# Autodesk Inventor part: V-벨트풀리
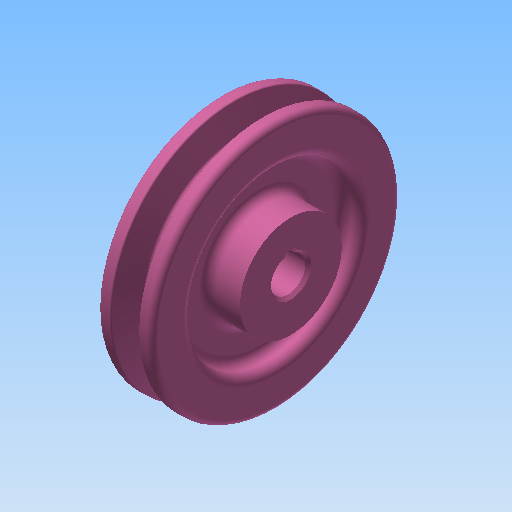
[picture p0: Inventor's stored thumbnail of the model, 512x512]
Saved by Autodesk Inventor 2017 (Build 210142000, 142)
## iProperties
Created: 2020-07
Part Number: V-벨트풀리
Material: 알루미늄 6061
Document SubType Name: Modeling
Designer: mduedu
Density: 2.71 g/cm^3
Mass: 204.704 g
Surface Area: 223.016 cm^2
Volume: 75.5367 cm^3
Appearance: 분홍색
Author: mduedu
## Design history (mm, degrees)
sketch "스케치1"
  geometry: L1 (-9.5, 0)-(9.5, 0); L2 (9.5, 0)-(9.5, 42.7); L3 (9.5, 42.7)-(-9.5, 42.7); L4 (-9.5, 42.7)-(-9.5, 0); L5 (0, 0)-(0, 42.7); L6 (-4.877, 42.7)-(-1.953, 33.7); L7 (-1.953, 33.7)-(1.953, 33.7); L8 (1.953, 33.7)-(4.877, 42.7); L9 (-9.5, 40)-(9.5, 40); 3 further points
  constraints: 18 end point, 8 point on line, 3 perpendicular, 2 midpoint, 2 parallel, 1 coincident, 1 horizontal, 1 other
  dimensions: "d0" = 85.4 diameter of L3 L1; "d2" = 8 distance of point (4, 40) point (-4, 40); "d3" = 2.7 distance between parallel lines of L9 L3; "d4" = 6.3 distance between parallel lines of L7 L9; "d5" = 36 deg angle of L8 L6; "d6" = 19 distance between parallel lines of L2 L4
revolve "회전1" sketch "스케치1" stored, may be unused: angle "d7" = 90 deg
fillet "모깎기1" dims "d8" = 0.5, "d9" = 1, "d10" = 2
sketch "스케치2"
  geometry: C1 r 17.5 at (0, 0); C2 r 29 at (0, 0); 1 further point
  constraints: 2 centre point, 2 coincident
  dimensions: "d11" = 35 diameter of C1; "d12" = 58 diameter of C2
extrude "돌출1" cut sketch "스케치2" distance "d13" = 6; taper "d14" = 0 deg
fillet "모깎기2" dims "d15" = 3
sketch "스케치3"
  geometry: C1 r 17.5 at (0, 0) reference; 1 further point
extrude "돌출2" join sketch "스케치3" distance "d16" = 5; taper "d17" = 0 deg
sketch "스케치4"
  geometry: L1 (-2, 5.657)-(2, 5.657); L2 (2, 5.657)-(2, 7.8); L3 (2, 7.8)-(-2, 7.8); L4 (-2, 7.8)-(-2, 5.657); A1 r 6 centre (0, 0) between (-2, 5.657) and (2, 5.657); 1 further point
  constraints: 8 end point, 2 parallel, 2 point on circle, 1 centre point, 1 coincident, 1 horizontal, 1 perpendicular
  dimensions: "d18" = 13.8 dimension on A1 L3; "d20" = 12 diameter of A1; "d21" = 4 distance of L2.end L3.end
extrude "돌출3" cut sketch "스케치4" stored distance "d22" = 5; taper "d23" = 0 deg
chamfer "모따기1" distance "d24" = 1; stored, may be unused: second distance "d25" = 2, angle "d26" = 45 deg
sketch "스케치5" dims "d27" = 73
  geometry: C1 r 2.5 at (0, 36.5); 2 further points
  constraints: 2 vertical alignment, 1 centre point, 1 coincident, 2 other
  dimensions: "d28" = 5 diameter of C1
extrude "돌출4" cut sketch "스케치5" distance "d29" = 0.5; taper "d30" = 0 deg
node "솔리드1"
mirror "대칭1"
node "투영된 루프1"
